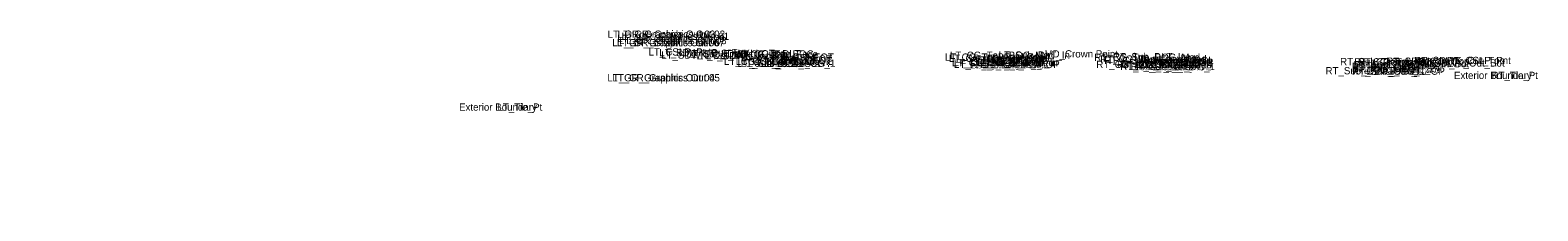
# Model space of a CAD drawing. Extents: x -26 to 6300, y -10 to 9528.
# Drawn here: x 1000 to 1207.5, y 500 to 524.9 of the extents above; entities that cross this region are included whole.
import ezdxf

# ---------------------------------------------------------------- set-up
doc = ezdxf.new("R2010")
doc.units = 0
doc.layers.add('Default', color=7, linetype='Continuous')

msp = doc.modelspace()

# ---------------------------------------------------------------- texts
at = {"layer": 'Default'}
for s, height, p in [('LT_GR_Graphics Out 03', 1, (1079.47, 523.83)), ('LT_GR_Graphics Out 06', 1, (1080.11, 522.67)), ('LT_GR_Graphics Out 07', 1, (1080.75, 522.67)), ('LT_GR_Graphics Out 09', 1, (1080.78, 523.25)), ('LT_GR_Graphics Out 02', 1, (1080.83, 523.83)), ('LT_GR_Graphics Out 08', 1, (1081.04, 522.96)), ('LT_GR_Graphics Out 01', 1, (1081.39, 523.54)), ('LT_CSLP_Pnt', 1, (1085.1, 521.39)), ('LT_SDWK_Out_Top', 1, (1086.58, 521.29)), ('LT_SDWK_Out_Bot', 1, (1086.83, 520.96)), ('LT_Sub_Trench_Out_DLT', 1, (1090.26, 521.14)), ('LT_SDWK_In_Top', 1, (1092.74, 521.19)), ('LT_SDWK_In_Bot', 1, (1092.99, 520.86)), ('LT_CG1_Shelf_Out', 1, (1095.48, 520.1)), ('LT_CG_Top_BOC', 1, (1096.81, 521.1)), ('LT_CG_Bot_BOC', 1, (1097.09, 520.1)), ('LT_CG_Top_Face', 1, (1097.34, 521.1)), ('LT_Sub_OEOT_CG_1', 1, (1097.36, 519.84)), ('LT_Sub_OEOP', 1, (1097.78, 519.86)), ('LT_CG_Top_Gut', 1, (1097.87, 520.6)), ('LT_PV2_OEOT', 1, (1100.99, 520.42)), ('LT_PV3_OEOT', 1, (1100.99, 520.17)), ('LT_Sub_OEOT', 1, (1101.04, 519.8)), ('LT_PV1_OEOT', 1, (1101.23, 520.67)), ('LT_CG_Bot_IE', 1, (1101.34, 520.09)), ('LT_CG_Top_Face_Med', 1, (1125.87, 520.67)), ('LT_CG_Top_Gut_Med', 1, (1126.42, 520.51)), ('LT_CG_Top_BOC_Med', 1, (1126.57, 520.92)), ('LT_CG_Bot_BOC_Med', 1, (1126.85, 519.92)), ('LT_CG_Bot_IE_Med', 1, (1127.09, 519.93)), ('LT_PV2_OEEOP', 1, (1129.29, 520.26)), ('LT_PV3_OEEOP', 1, (1129.29, 520.01)), ('LT_PV2_IEEOP', 1, (1130.05, 520.26)), ('LT_CG1_Shelf_In', 1, (1130.71, 519.92)), ('LT_PV2_PGL', 1, (1131.26, 520.26)), ('LT_PV1_PGL', 1, (1131.5, 520.51)), ('LT_Sub_DLT_In', 1, (1133.26, 520.96)), ('MD_Crown Point', 1, (1139.58, 521.12)), ('RT_CG_Top_BOC_Med', 1, (1146.43, 520.65)), ('RT_CG_Top_Face_Med', 1, (1147.25, 520.4)), ('RT_CG_Top_Gut_Med', 1, (1147.8, 520.23)), ('RT_Sub_DLT_In', 1, (1149.01, 520.75)), ('RT_PV2_OEEOP', 1, (1152.17, 519.97)), ('RT_PV2_IEEOP', 1, (1152.93, 519.97)), ('RT_PV2_PGL', 1, (1154.15, 519.97)), ('RT_PV1_PGL', 1, (1154.38, 520.22)), ('RT_Sub_Trench_Out_DLT', 1, (1180.26, 520.06)), ('RT_CG_Top_Face', 1, (1182.22, 520.02)), ('RT_CG_Top_BOC', 1, (1182.69, 520.02)), ('RT_SDWK_In_Top', 1, (1186.62, 520.11)), ('RT_SDWK_In_Bot', 1, (1186.87, 519.77)), ('RT_SDWK_Out_Top', 1, (1190.46, 520.21)), ('RT_SDWK_Out_Bot', 1, (1190.71, 519.87)), ('RT_CSLP_Pnt', 1, (1194.98, 520.21)), ('LT_GR_Graphics Out 04', 1, (1079.43, 517.83)), ('LT_GR_Graphics Out 05', 1, (1080.12, 517.83)), ('LT_Sub_IEOT_CG_1', 1, (1127.13, 519.68)), ('LT_Sub_OEEOP', 1, (1129.33, 519.64)), ('LT_Sub_IEEOP', 1, (1130.09, 519.64)), ('LT_Sub_PGL', 1, (1131.31, 519.64)), ('LT_Sub_IEOP', 1, (1133.05, 519.67)), ('RT_CG_Bot_BOC_Med', 1, (1146.71, 519.67)), ('RT_CG1_Shelf_In', 1, (1149.57, 519.68)), ('RT_CG_Bot_IE_Med', 1, (1149.98, 519.63)), ('RT_Sub_IEOT_CG_1', 1, (1150.01, 519.38)), ('RT_Sub_IEOP', 1, (1151.42, 519.43)), ('RT_PV3_OEEOP', 1, (1152.17, 519.72)), ('RT_Sub_OEEOP', 1, (1152.21, 519.34)), ('RT_Sub_IEEOP', 1, (1152.97, 519.34)), ('RT_Sub_PGL', 1, (1154.19, 519.34)), ('RT_Sub_OEOT_CG_1', 1, (1178.25, 518.8)), ('RT_PV2_OEOT', 1, (1181.87, 519.39)), ('RT_PV3_OEOT', 1, (1181.87, 519.14)), ('RT_Sub_OEOT', 1, (1181.92, 518.76)), ('RT_PV1_OEOT', 1, (1182.11, 519.64)), ('RT_CG_Bot_IE', 1, (1182.22, 519.05)), ('RT_CG1_Shelf_Out', 1, (1182.36, 518.99)), ('RT_CG_Top_Gut', 1, (1182.75, 519.52)), ('RT_CG_Bot_BOC', 1, (1182.97, 519)), ('RT_Sub_OEOP', 1, (1185.17, 518.74)), ('Exterior Boundary', 1, (1195.93, 518.16)), ('RT_Tie_Pt', 1, (1201.09, 518.16)), ('Exterior Boundary', 1, (1059.02, 513.79)), ('LT_Tie_Pt', 1, (1064.3, 513.79)), ('-', 0.0001, (1000, 500))]:
    msp.add_text(s, height=height, dxfattribs=at).set_placement(p)

doc.saveas('drawing.dxf')
